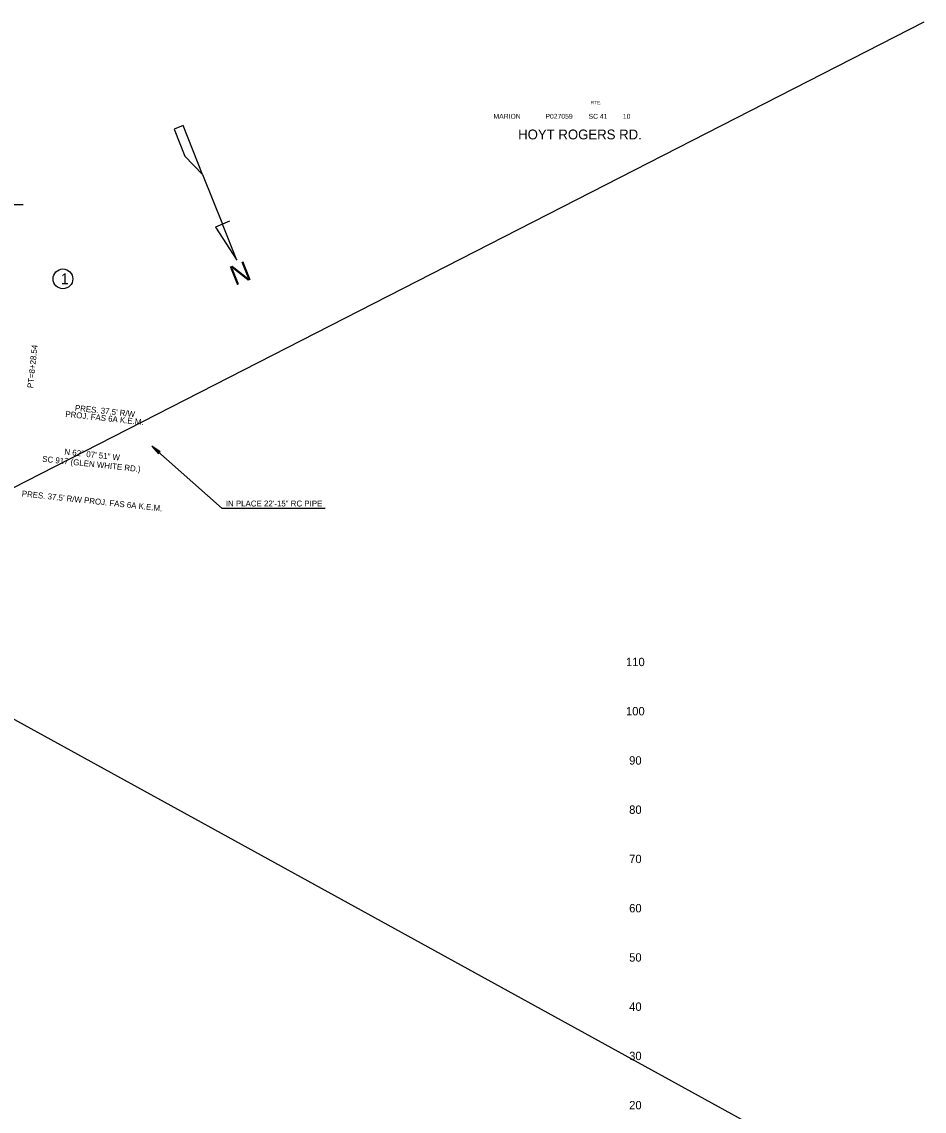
# Model space of a CAD drawing. Extents: x 2522404 to 2525275, y 885432 to 893540.
# Drawn here: x 2524359 to 2525275, y 891287 to 892393 of the extents above; entities that cross this region are included whole.
import ezdxf

# ---------------------------------------------------------------- set-up
doc = ezdxf.new("R2010")
doc.units = 0
for name, color, linetype in [('Default', 7, 'Continuous'), ('RD_DDB_ElevTX', 7, 'Continuous'), ('RD_DDB_Profile_Lbl', 7, 'Continuous'), ('RD_EX_Misc', 7, 'Continuous'), ('RD_HC_Cl', 7, 'Continuous'), ('RD_HC_TX_Sta50', 7, 'Continuous'), ('RD_HY_TX1', 7, 'Continuous'), ('RD_PD_RW_TX', 7, 'Continuous'), ('RD_SHT_IplotShp', 7, 'Continuous'), ('RD_Sketch8', 7, 'Continuous')]:
    doc.layers.add(name, color=color, linetype=linetype)

# ---------------------------------------------------------------- blocks, each defined once
blk = doc.blocks.new('ah_')
at = {"layer": 'Default'}
blk.add_lwpolyline([(0, 0), (-1.4, -10.4), (0, -8.8), (1.5, -10.4)], close=True, dxfattribs=at)
blk = doc.blocks.new('ah4')
at = {"layer": 'Default', "rotation": -90.00000000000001}
blk.add_blockref('ah_', (0, 0), dxfattribs=at)

msp = doc.modelspace()

# ---------------------------------------------------------------- linework, layer by layer
at = {"layer": 'RD_DDB_ElevTX'}
for p, q in [((2523122.7, 891292.5), (2525274.9, 892393.1)), ((2523105.6, 892369.2), (2525153.6, 891243.7))]:
    msp.add_line(p, q, dxfattribs=at)
at = {"layer": 'RD_EX_Misc'}
msp.add_circle((2524400.6, 892132.1), 10, dxfattribs=at)
at = {"layer": 'RD_HY_TX1'}
msp.add_line((2524490.7, 891962.3), (2524562.3, 891898.9), dxfattribs=at)
msp.add_lwpolyline([(2524666.9, 891898.9), (2524562.3, 891898.9)], dxfattribs=at)
at = {"layer": 'RD_PD_RW_TX'}
msp.add_line((2524236.4, 892207.5), (2524360.3, 892207.5), dxfattribs=at)
at = {"layer": 'RD_Sketch8'}
for p, q in [((2524522.5, 892287.7), (2524513.4, 892284.1)), ((2524513.4, 892284.1), (2524524.4, 892256.5)), ((2524542.4, 892238.1), (2524522.5, 892287.7)), ((2524524.3, 892256.8), (2524542.4, 892238.1)), ((2524524.4, 892256.5), (2524524.3, 892256.8)), ((2524542.4, 892238.1), (2524562.5, 892187.6)), ((2524569.8, 892190.5), (2524562.5, 892187.6)), ((2524562.5, 892187.6), (2524555.3, 892184.7)), ((2524555.3, 892184.7), (2524555.4, 892184.3)), ((2524555.3, 892184.7), (2524577.1, 892151.2)), ((2524577.1, 892151.2), (2524562.5, 892187.6)), ((2524577.1, 892151.2), (2524577.1, 892151.2))]:
    msp.add_line(p, q, dxfattribs=at)

# ---------------------------------------------------------------- block references
at = {"layer": 'RD_HY_TX1', "rotation": 138.18745160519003}
msp.add_blockref('ah4', (2524490.7, 891962.3), dxfattribs=at)

# ---------------------------------------------------------------- texts
at = {"layer": 'RD_DDB_Profile_Lbl'}
msp.add_text('1', height=11, dxfattribs=at).set_placement((2524398.4, 892126.6))
at = {"layer": 'RD_EX_Misc'}
for s, height, p in [('RTE.', 3.5, (2524936.3, 892309.3)), ('MARION', 5, (2524837.7, 892294.6)), ('P027059', 5, (2524890.4, 892294.6)), ('SC 41', 5, (2524934.2, 892294.6)), ('10', 5, (2524969, 892294.6)), ('HOYT ROGERS RD.', 10, (2524862.7, 892273.7))]:
    msp.add_text(s, height=height, dxfattribs=at).set_placement(p)
at = {"layer": 'RD_HC_Cl'}
for s, rotation, p in [('PT=8+28.54', 83.915, (2524370.3, 892020.9)), ('N 62%%d 07\' 51" W', 353.915, (2524401.8, 891953.7)), ('SC 917 (GLEN WHITE RD.)', 353.915, (2524379.3, 891946.5))]:
    msp.add_text(s, height=6, rotation=rotation, dxfattribs=at).set_placement(p)
at = {"layer": 'RD_HC_TX_Sta50'}
for s, p in [('110', (2524972.2, 891738.9)), ('100', (2524972.2, 891688.9)), ('90', (2524975.4, 891638.9)), ('80', (2524975.4, 891588.9)), ('70', (2524975.4, 891538.9)), ('60', (2524975.4, 891488.9)), ('50', (2524975.4, 891438.9)), ('40', (2524975.4, 891388.9)), ('30', (2524975.4, 891338.9)), ('20', (2524975.4, 891288.9))]:
    msp.add_text(s, height=8.5, dxfattribs=at).set_placement(p)
at = {"layer": 'RD_HY_TX1'}
msp.add_text('IN PLACE 22\'-15" RC PIPE', height=6, dxfattribs=at).set_placement((2524565.9, 891901))
at = {"layer": 'RD_SHT_IplotShp'}
for s, p in [("PRES. 37.5' R/W ", (2524412.5, 891998.2)), ('PROJ. FAS 6A K.E.M.', (2524402.8, 891992)), ("PRES. 37.5' R/W PROJ. FAS 6A K.E.M.", (2524358.6, 891911.2))]:
    msp.add_text(s, height=6, rotation=353.9134, dxfattribs=at).set_placement(p)
at = {"layer": 'RD_Sketch8'}
msp.add_text('N', height=20, rotation=201.7842, dxfattribs=at).set_placement((2524585.8, 892150.7))

doc.saveas('drawing.dxf')
